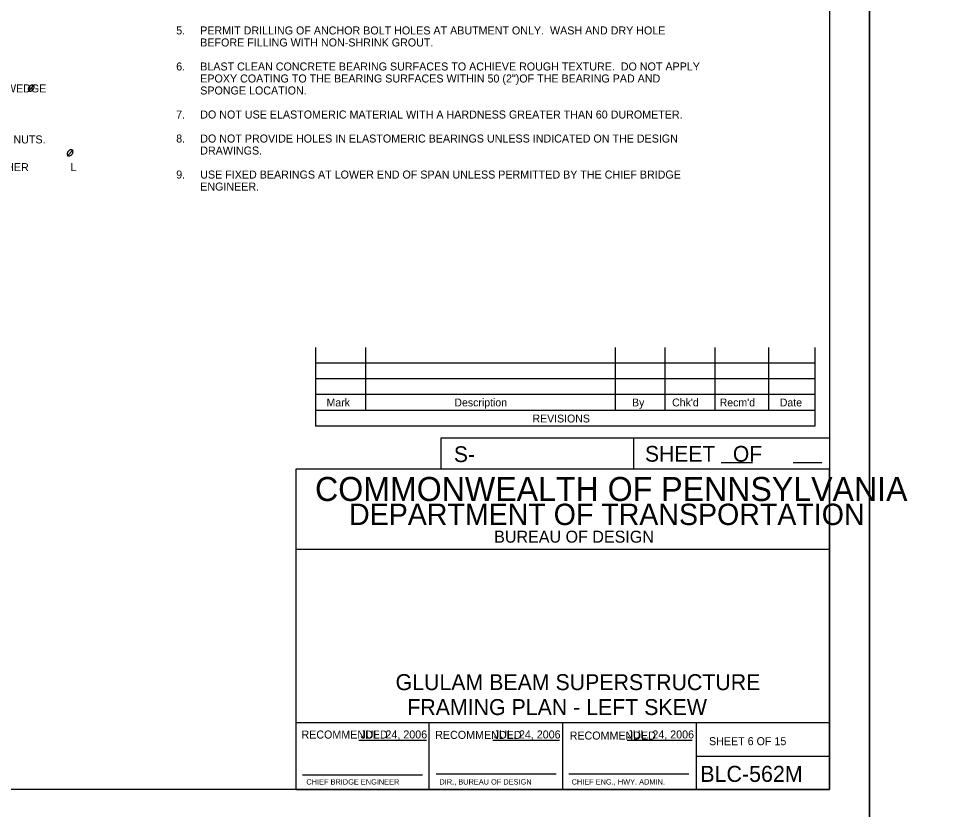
# Model space of a CAD drawing. Extents: x 638263 to 640360, y 293683 to 298655.
# Drawn here: x 638957.6 to 639303.1, y 294879 to 295175.4 of the extents above; entities that cross this region are included whole.
import ezdxf

# ---------------------------------------------------------------- set-up
doc = ezdxf.new("R2010")
doc.units = 0
for name, color, linetype in [('2', 7, 'Continuous'), ('4', 7, 'Continuous'), ('PLT-BNDY', 7, 'Continuous')]:
    doc.layers.add(name, color=color, linetype=linetype)

msp = doc.modelspace()

# ---------------------------------------------------------------- linework, layer by layer
at = {"layer": '2'}
for p, q in [((639261.46, 295450.46), (639261.46, 294886.46)), ((639068.92, 295052.15), (639068.92, 295022.62)), ((639087.62, 295052.15), (639087.62, 295028.53)), ((639181.13, 295052.15), (639181.13, 295028.53)), ((639199.83, 295052.15), (639199.83, 295028.53)), ((639218.53, 295052.15), (639218.53, 295028.53)), ((639238.59, 295052.15), (639238.59, 295028.53)), ((639255.94, 295052.15), (639255.94, 295022.62)), ((639255.94, 295046.24), (639068.92, 295046.24)), ((639255.94, 295040.34), (639068.92, 295040.34)), ((639255.94, 295034.43), (639068.92, 295034.43)), ((639255.94, 295028.53), (639068.92, 295028.53)), ((639255.94, 295022.62), (639068.92, 295022.62)), ((639261.46, 295018.11), (639115.78, 295018.11)), ((639115.78, 295018.11), (639115.78, 295006.46)), ((639188.09, 295018.11), (639188.09, 295006.46)), ((639220.95, 295009), (639232.6, 295009)), ((639247.83, 295009), (639258.56, 295009)), ((639261.46, 295006.46), (639061.46, 295006.46)), ((639061.46, 295006.46), (639061.46, 294886.46)), ((639261.46, 294886.46), (639261.46, 295006.46)), ((639261.46, 294976.46), (639061.46, 294976.46)), ((639261.46, 294911.46), (639061.46, 294911.46)), ((639111.46, 294886.46), (639111.46, 294911.46)), ((639161.46, 294911.46), (639161.46, 294886.46)), ((639211.46, 294911.46), (639211.46, 294886.46)), ((639085.11, 294904.94), (639110.49, 294904.94)), ((639135.38, 294904.94), (639160.27, 294904.94)), ((639185.65, 294904.94), (639210.06, 294904.94)), ((639211.46, 294898.96), (639261.46, 294898.96)), ((639063.96, 294891.96), (639108.96, 294891.96)), ((639114.08, 294892.33), (639159.08, 294892.33)), ((639163.83, 294892.33), (639208.83, 294892.33)), ((639261.46, 294886.46), (638475.46, 294886.46)), ((639061.46, 294886.46), (639261.46, 294886.46))]:
    msp.add_line(p, q, dxfattribs=at)
at = {"layer": '4'}
for p, q in [((638961.19, 295147.98), (638963.43, 295150.43)), ((638975.77, 295123.74), (638978.01, 295126.19))]:
    msp.add_line(p, q, dxfattribs=at)
for points in [[(638963.2, 295150.19), (638963.02, 295150.32), (638962.85, 295150.37), (638962.63, 295150.39), (638962.5, 295150.39), (638962.29, 295150.34), (638962.09, 295150.25), (638961.95, 295150.17), (638961.69, 295149.96), (638961.48, 295149.69), (638961.35, 295149.44), (638961.28, 295149.21), (638961.26, 295148.99), (638961.28, 295148.81), (638961.37, 295148.54), (638961.47, 295148.41), (638961.66, 295148.26), (638961.95, 295148.19), (638962.28, 295148.2), (638962.7, 295148.39), (638963, 295148.66), (638963.23, 295148.97), (638963.38, 295149.31), (638963.43, 295149.67), (638963.37, 295149.91), (638963.21, 295150.19)], [(638977.78, 295125.95), (638977.6, 295126.09), (638977.42, 295126.14), (638977.21, 295126.16), (638977.08, 295126.16), (638976.87, 295126.11), (638976.67, 295126.02), (638976.53, 295125.94), (638976.27, 295125.73), (638976.06, 295125.46), (638975.93, 295125.21), (638975.86, 295124.97), (638975.84, 295124.76), (638975.86, 295124.57), (638975.95, 295124.31), (638976.05, 295124.17), (638976.24, 295124.03), (638976.53, 295123.96), (638976.86, 295123.97), (638977.28, 295124.16), (638977.58, 295124.42), (638977.81, 295124.74), (638977.96, 295125.07), (638978.01, 295125.44), (638977.94, 295125.67), (638977.79, 295125.95)]]:
    msp.add_spline(points, degree=3, dxfattribs=at)
at = {"layer": 'PLT-BNDY'}
for points in [[(638435.46, 295465.46), (639276.46, 295465.46), (639276.46, 294871.46), (638435.46, 294871.46)], [(639276.46, 295465.46), (640117.46, 295465.46), (640117.46, 294871.46), (639276.46, 294871.46)]]:
    msp.add_lwpolyline(points, close=True, dxfattribs=at)

# ---------------------------------------------------------------- texts
at = {"layer": '2'}
for s, height, p in [('Mark', 2.952, (639073.02, 295030.03)), ('Description', 2.9523, (639120.92, 295030.03)), ('By', 2.952, (639187.49, 295030.03)), ("Chk'd", 2.952, (639202.52, 295030.03)), ("Recm'd", 2.953, (639220.33, 295030.03)), ('Date', 2.952, (639242.86, 295030.03)), ('REVISIONS', 2.952, (639150.2, 295024.01)), ('S-', 5.905, (639120.73, 295009.17)), ('COMMONWEALTH OF PENNSYLVANIA', 9, (639068.71, 294994.58)), ('DEPARTMENT OF TRANSPORTATION', 8.0002, (639081.46, 294985.58)), ('BUREAU OF DESIGN', 4.5, (639135.83, 294978.96)), ('FRAMING PLAN - LEFT SKEW', 5.9728, (639103.29, 294914.37)), ('RECOMMENDED', 3, (639063.61, 294905.57)), ('JUL. 24, 2006', 3, (639085.74, 294905.6)), ('RECOMMENDED', 3, (639113.74, 294905.44)), ('JUL. 24, 2006', 3, (639135.74, 294905.6)), ('RECOMMENDED', 3, (639164.11, 294905.19)), ('JUL. 24, 2006', 3, (639185.74, 294905.6)), ('SHEET 6 OF 15', 3, (639216.33, 294903.08)), ('BLC-562M', 6, (639213.08, 294889.33)), ('CHIEF BRIDGE ENGINEER', 2.0002, (639065.46, 294888.33)), ('DIR., BUREAU OF DESIGN', 2.0002, (639115.33, 294888.33)), ('CHIEF ENG., HWY. ADMIN.', 2.0002, (639164.83, 294888.33))]:
    msp.add_text(s, height=height, dxfattribs=at).set_placement(p)
msp.add_text('SHEET   OF', height=5.907, rotation=360, dxfattribs=at).set_placement((639192.35, 295009.31))
at = {"layer": '4'}
for s, height, p in [('5.', 3, (639016.68, 295169.41)), ('PERMIT DRILLING OF ANCHOR BOLT HOLES AT ABUTMENT ONLY.  WASH AND DRY HOLE', 3, (639025.68, 295169.41)), ('BEFORE FILLING WITH NON-SHRINK GROUT.', 3, (639025.68, 295164.91)), ('6.', 3, (639016.68, 295155.91)), ('BLAST CLEAN CONCRETE BEARING SURFACES TO ACHIEVE ROUGH TEXTURE.  DO NOT APPLY', 3, (639025.68, 295155.91)), ('EPOXY COATING TO THE BEARING SURFACES WITHIN 50 (2")OF THE BEARING PAD AND', 3, (639025.68, 295151.41)), ('FOR CONC. ABUT. USE: 38.1 (1 1/2")  STEEL SWEDGE', 3, (638865.19, 295147.69)), ('SPONGE LOCATION.', 3, (639025.68, 295146.91)), ('7.', 3, (639016.68, 295137.91)), ('DO NOT USE ELASTOMERIC MATERIAL WITH A HARDNESS GREATER THAN 60 DUROMETER.', 3, (639025.68, 295137.91)), ('TURN AND PEEN BOLT THREADS AT FACE OF NUTS.', 3, (638865.19, 295128.57)), ('8.', 3, (639016.68, 295128.91)), ('DO NOT PROVIDE HOLES IN ELASTOMERIC BEARINGS UNLESS INDICATED ON THE DESIGN', 3, (639025.68, 295128.91)), ('DRAWINGS.', 3, (639025.68, 295124.41)), ('305 (1\'-0") LONG LAG SCREW, 10 (3/8") P WASHER', 3, (638865.29, 295118.18)), ('L', 3, (638977.11, 295118.18)), ('9.', 3, (639016.68, 295115.41)), ('USE FIXED BEARINGS AT LOWER END OF SPAN UNLESS PERMITTED BY THE CHIEF BRIDGE ', 3, (639025.68, 295115.41)), ('ENGINEER.', 3, (639025.68, 295110.91)), ('GLULAM BEAM SUPERSTRUCTURE', 5.9728, (639098.89, 294923.71))]:
    msp.add_text(s, height=height, dxfattribs=at).set_placement(p)

doc.saveas('drawing.dxf')
